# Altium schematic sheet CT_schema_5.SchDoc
size 368 x 309 mm
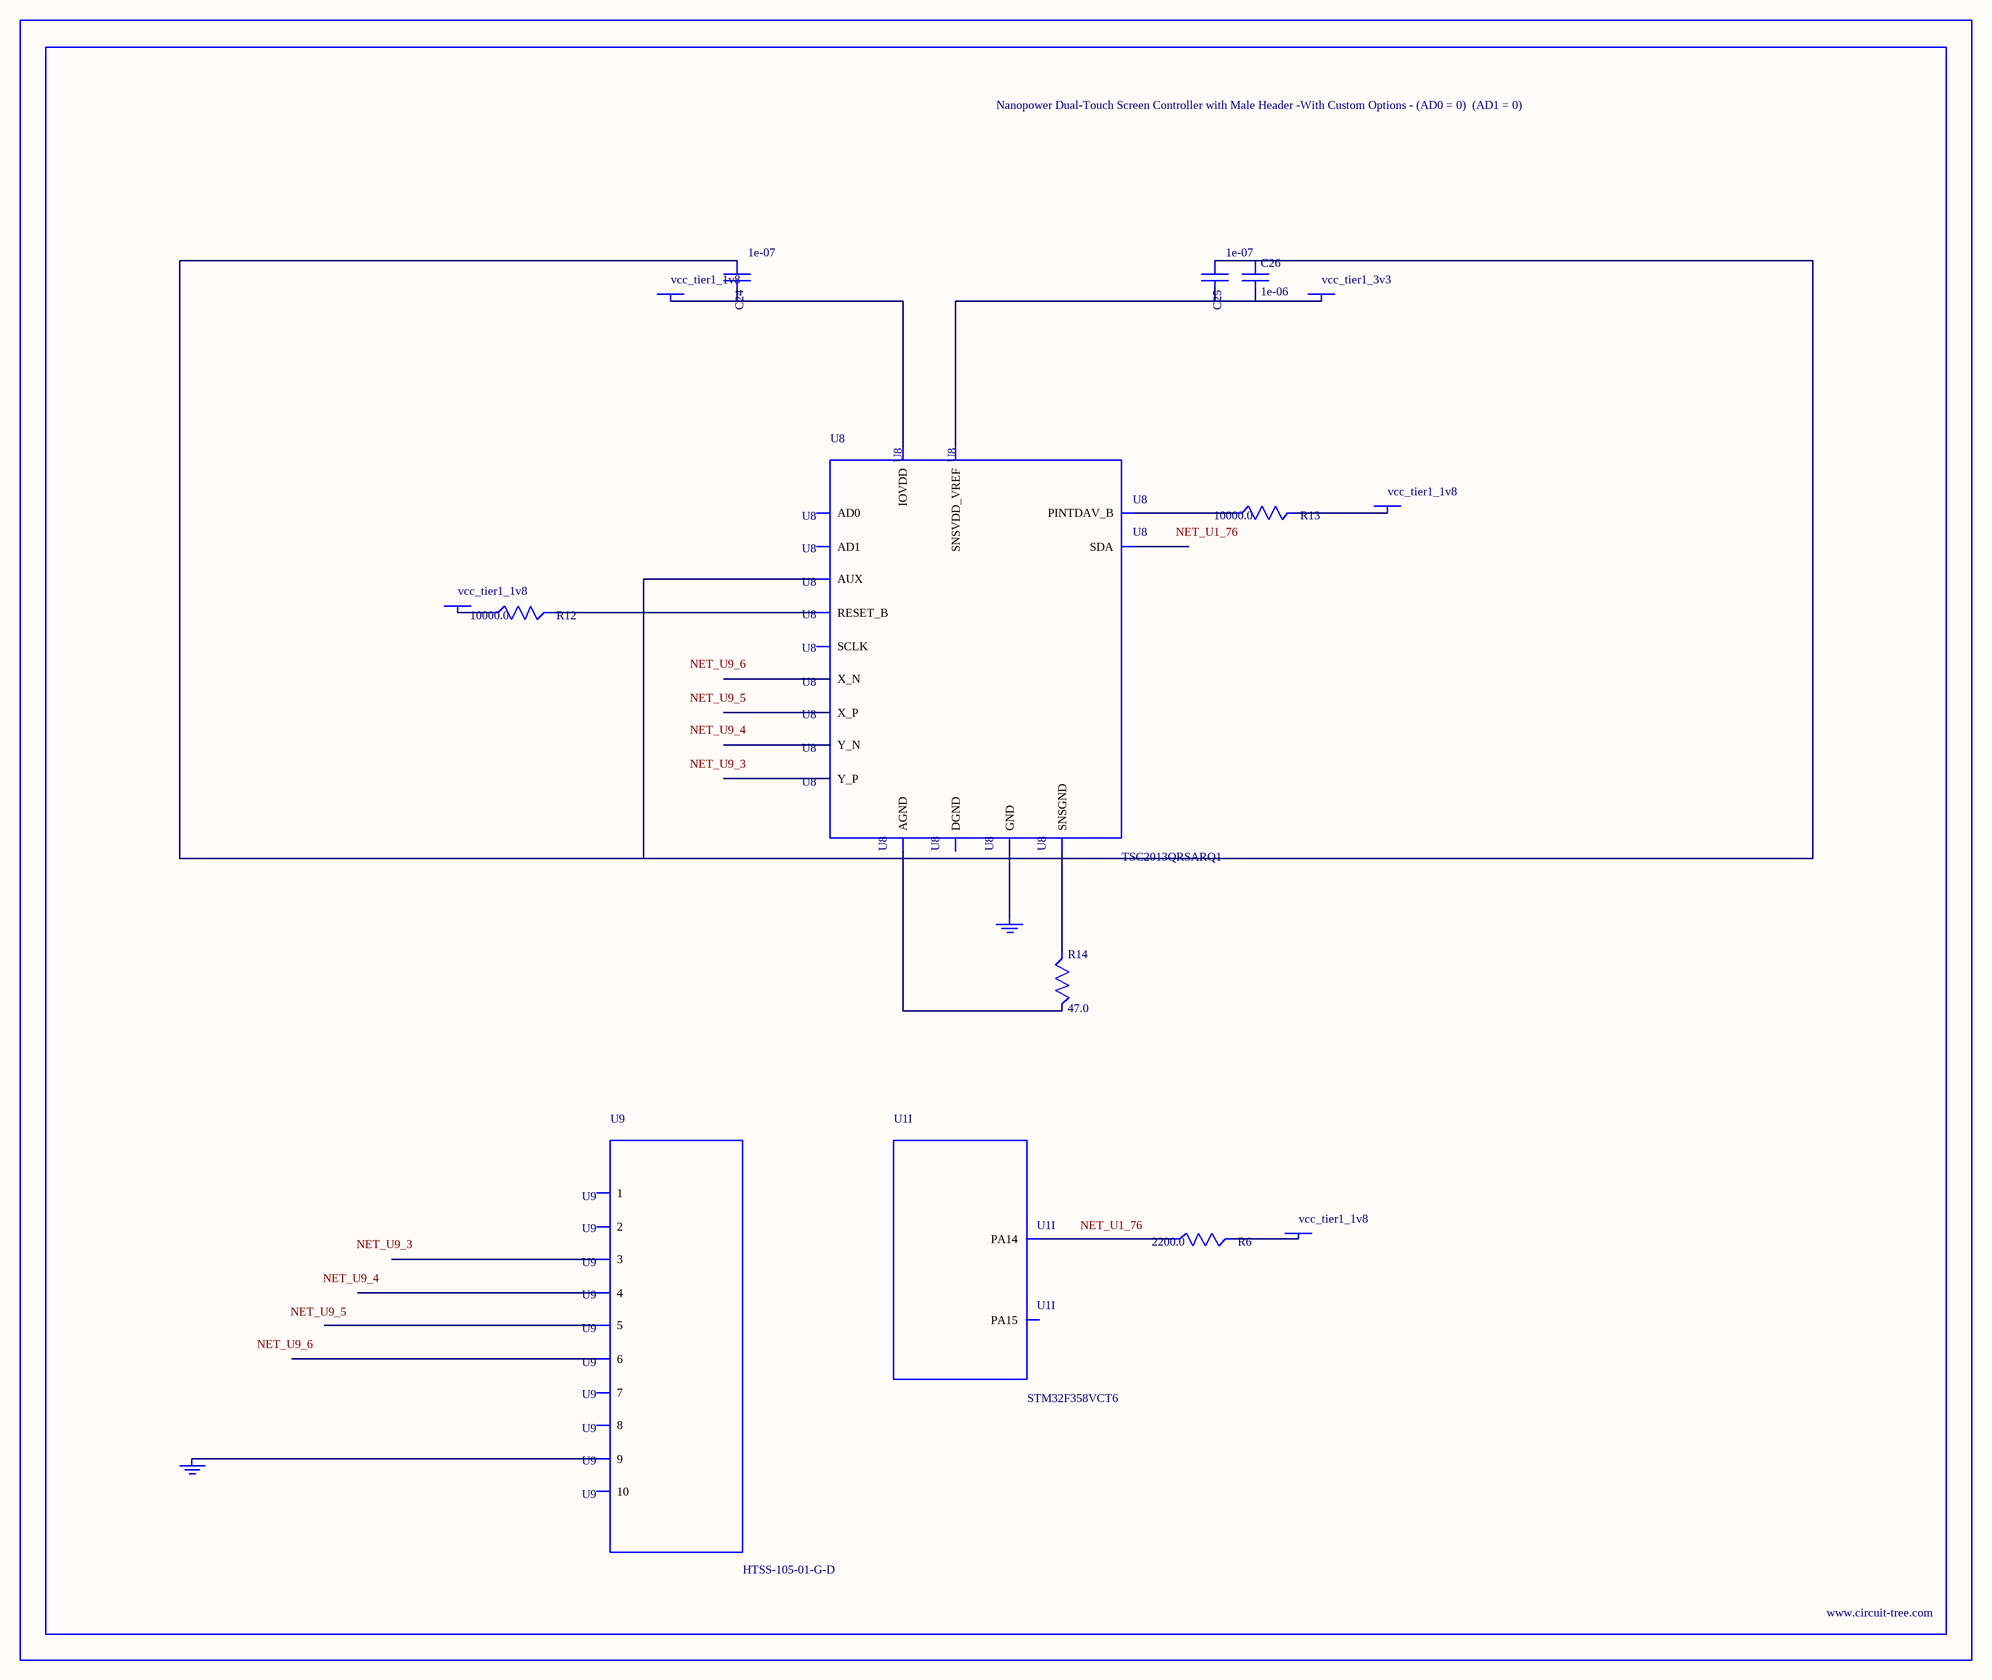
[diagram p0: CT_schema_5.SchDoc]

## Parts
BORDER4  (no value)
C24  1e-07  [C0402]
C25  1e-07  [C0402]
C26  1e-06  [C0603]
GND_INSTANCE_4_0  (no value)
GND_INSTANCE_4_1  (no value)
POWER_INSTANCE_4_0  vcc_tier1_1v8
POWER_INSTANCE_4_1  vcc_tier1_1v8
POWER_INSTANCE_4_2  vcc_tier1_1v8
POWER_INSTANCE_4_3  vcc_tier1_3v3
POWER_INSTANCE_4_4  vcc_tier1_1v8
R6  2200.0  [R0603]
R12  10000.0  [R0603]
R13  10000.0  [R0603]
R14  47.0  [R0603]
U1  STM32F358VCT6  [LQFP100]  (part I of 10)
U8  TSC2013QRSARQ1  [QFN65P400X400X100-17N]
U9  HTSS-105-01-G-D  [HTSS-105-01-G-D]

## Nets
NetC24_1: C24.1 C25.1 C26.1 R14.1 R14.2 U8.8(AUX) U8.9(AGND) U8.15(SNSGND)
NetC24_2: C24.2 POWER_INSTANCE_4_2.0(PWR) U8.7(IOVDD)
NetC25_2: C25.2 C26.2 POWER_INSTANCE_4_3.0(PWR) U8.10(SNSVDD_VREF)
NetGND_INSTANCE_4_0_0: GND_INSTANCE_4_0.0(GND) U8.17(GND)
NetGND_INSTANCE_4_1_0: GND_INSTANCE_4_1.0(GND) U9.9
NetPOWER_INSTANCE_4_0_0: POWER_INSTANCE_4_0.0(PWR) R13.2
NetPOWER_INSTANCE_4_1_0: POWER_INSTANCE_4_1.0(PWR) R12.1
NetPOWER_INSTANCE_4_4_0: POWER_INSTANCE_4_4.0(PWR) R6.2
NetR6_1: R6.1 U1.76(PA14)
NetR12_2: R12.2 U8.5(RESET_B)
NetR13_1: R13.1 U8.4(PINTDAV_B)

Not connected (* = marked no-connect by the designer): U1 77(PA15); U8 1(SDA) 2(SCLK) 3(AD1) 6(DGND) 11(X_P) 12(Y_P) 13(X_N) 14(Y_N) 16(AD0); U9 1 2 3 4 5 6 7 8 10

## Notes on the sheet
- Labels drawn without touching a wire or pin: NET_U1_76, NET_U9_3, NET_U9_4, NET_U9_5, NET_U9_6

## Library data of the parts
BORDER4 = BORDER_PAGE4
C24 C25 = C0402C104K3RACTU
C26 = C0603C105K3RACTU
GND_INSTANCE_4_0 GND_INSTANCE_4_1 = GND
POWER_INSTANCE_4_0-POWER_INSTANCE_4_4 = PWR
R6 = RC0603JR-072K2L
R12 R13 = RC0603JR-0710KL
R14 = RC0603JR-0747RL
